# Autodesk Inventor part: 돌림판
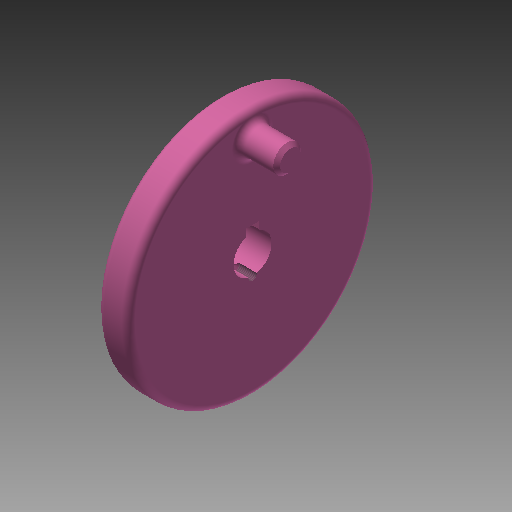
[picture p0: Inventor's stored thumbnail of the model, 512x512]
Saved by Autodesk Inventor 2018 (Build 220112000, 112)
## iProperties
Created: 2019-09
Part Number: 돌림판
Material: 알루미늄 6061
Document SubType Name: Modeling
Designer: mduedu
Density: 2.71 g/cm^3
Mass: 83.7217 g
Surface Area: 107.333 cm^2
Volume: 30.8936 cm^3
Appearance: 분홍색
Author: mduedu
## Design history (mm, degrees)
sketch "스케치1"
  geometry: L1 (0, 0)-(9, 0); L2 (9, 0)-(9, 36); L3 (9, 36)-(0, 36); L4 (0, 23)-(4, 23); L5 (4, 23)-(4, 10); L6 (4, 10)-(0, 10); L7 (0, 36)-(0, 23); L8 (0, 10)-(0, 0)
  constraints: 16 end point, 4 parallel, 2 horizontal, 2 perpendicular, 1 collinear
  dimensions: "d0" = 72 diameter of L3 L1; "d2" = 9 distance of L2.end L3.end; "d3" = 4 distance between parallel lines of L7 L5; "d4" = 20 diameter of L6 L1; "d5" = 46 diameter of L4 L1
revolve "회전1" sketch "스케치1" stored, may be unused: angle "d6" = 90 deg
fillet "모깎기1" dims "d7" = 3
sketch "스케치2"
  geometry: C1 r 4 at (0, 29); 1 further point
  constraints: 1 centre point, 1 vertical alignment
  dimensions: "d8" = 8 diameter of C1; "d9" = 29 distance of C1.centre point (0, 0)
extrude "돌출1" join sketch "스케치2" distance "d10" = 11; taper "d11" = 0 deg
fillet "모깎기2" dims "d12" = 2
fillet "모깎기3" dims "d13" = 2
chamfer "모따기1" distance "d14" = 1; stored, may be unused: second distance "d15" = 2, angle "d16" = 45 deg
sketch "스케치3"
  geometry: L1 (-2, 5.123)-(2, 5.123); L2 (2, 5.123)-(2, 7.3); L3 (2, 7.3)-(-2, 7.3); L4 (-2, 7.3)-(-2, 5.123); A1 r 5.5 centre (0, 0) between (-2, 5.123) and (2, 5.123); 1 further point
  constraints: 8 end point, 2 parallel, 2 point on circle, 1 centre point, 1 coincident, 1 horizontal, 1 perpendicular
  dimensions: "d17" = 11 diameter of A1; "d18" = 4 distance of L2.end L3.end; "d19" = 12.8 dimension on A1 L3
extrude "돌출2" cut sketch "스케치3" extent not by distance; stored distance "d20" = 11; taper "d21" = 0 deg
chamfer "모따기2" distance "d22" = 0.5; stored, may be unused: second distance "d23" = 2, angle "d24" = 45 deg
sketch "스케치4"
  geometry: A1 r 5.5 centre (0, 0) between (-2, 5.123) and (2, 5.123) reference; 2 further points
  constraints: 1 point on circle
hole "구멍1" sketch "스케치4" at (0, -5.5) diameter "d25" = 2.459; stored, may be unused: countersink angle "d29" = 90 deg, drill point angle "d31" = 118 deg; dims "d26" = 6, "d27" = 4, "d28" = 2, "d30" = 5
node "솔리드1"
